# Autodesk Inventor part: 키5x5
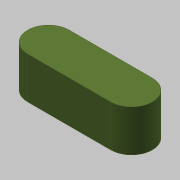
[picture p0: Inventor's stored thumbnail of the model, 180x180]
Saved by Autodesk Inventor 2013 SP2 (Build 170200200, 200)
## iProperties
Created: 2011-04
Part Number: 키5x5
Document SubType Name: Modeling
Designer: pww
Density: 7.86 g/cm^3
Material: 강철, 연강
Author: pww
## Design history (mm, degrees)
sketch "스케치1"
  geometry: L1 (-5, -2.5)-(5, -2.5); L2 (5, 2.5)-(-5, 2.5); A1 r 2.5 centre (-5, 0) between (-5, 2.5) and (-5, -2.5); A2 r 2.5 centre (5, 0) between (5, -2.5) and (5, 2.5); 1 further point
  constraints: 4 end point, 4 point on circle, 2 centre point
extrude "돌출1" new body sketch "스케치1" distance "d0" = 5; taper "d1" = 0 deg
node "솔리드1"
